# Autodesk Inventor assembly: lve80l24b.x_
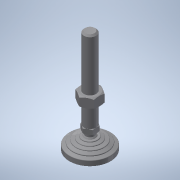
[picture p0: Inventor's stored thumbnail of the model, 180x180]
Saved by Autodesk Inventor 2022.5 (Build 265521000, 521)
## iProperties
Part Number: lve80l24b.x_
Material: 一般
Document SubType Name: Assembly
Designer: ImaoCorp
Sending System: SOLIDWORKS 2017-2017317
MC: AMD64
MC_MODEL: Intel64 Family 6 Model 60 Stepping 3, GenuineIntel
OS: Windows_NT
FRU: Parasolid Version 29.0, build 201,  4-17-2017
FORMAT: text
GUISE: transmit
KEY: lve80l24b
FILE: lve80l24b.x_t
DATE: Mon Jul 01 18:21:26 2019
Author: ImaoCorp
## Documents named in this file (3)
- X:\14_SW2022-Inv2022\00_全2023-1023新製品(TCC)まで\l\lve80l24b\LVE80L24B.iam
- X:\14_SW2022-Inv2022\00_全2023-1023新製品(TCC)まで\l\lve80l24b\lve80l24b_01.ipt
- X:\14_SW2022-Inv2022\00_全2023-1023新製品(TCC)まで\l\lve80l24b\lve80l24b_02.ipt
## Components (2 placed, 2 different names)
1. lve80l24b_01
2. lve80l24b_02
